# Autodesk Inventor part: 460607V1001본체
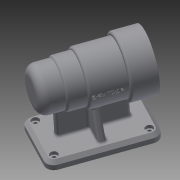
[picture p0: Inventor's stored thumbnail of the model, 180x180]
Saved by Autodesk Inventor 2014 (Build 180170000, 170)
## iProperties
Created: 2016-06
Part Number: 460607V1001본체
Material: 일반
Document SubType Name: Modeling
Designer: SEC
Density: 1 g/cm^3
Appearance: 기본값
Author: SEC
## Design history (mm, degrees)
sketch "스케치1"
  geometry: L1 (-56, 0)-(56, 0); L2 (-56, 0)-(-56, 25); L3 (-56, 25)-(-31, 25); L4 (-31, 25)-(-31, 27); L5 (-31, 27)-(-11, 27); L6 (-11, 27)-(-11, 30); L7 (-11, 30)-(28, 30); L8 (28, 30)-(28, 34); L9 (28, 34)-(56, 34); L10 (56, 34)-(56, 0); 2 further points
  constraints: 20 end point, 5 parallel, 4 perpendicular, 1 coincident, 1 horizontal, 1 midpoint
  dimensions: "d0" = 112 distance of L1.start L1.end; "d1" = 25 distance of L2.end L3.end; "d2" = 45 distance from line of L5.end L2; "d3" = 84 distance between parallel lines of L8 L2; "d4" = 50 diameter of L3 L1; "d5" = 54 diameter of L5 L1; "d6" = 60 diameter of L7 L1; "d7" = 68 diameter of L9 L1
revolve "회전1" sketch "스케치1" stored, may be unused: angle "d8" = 90 deg
node "작업 평면1"
sketch "스케치2"
  geometry: L1 (56, 35)-(-56, 35); L2 (-56, 35)-(-56, -35); L3 (-56, -35)-(56, -35); L4 (56, -35)-(56, 35); L5 (56, 35)-(-56, -35); L6 (-56, 35)-(56, -35); 1 further point
  constraints: 12 end point, 2 midpoint, 2 parallel, 1 horizontal, 1 perpendicular
  dimensions: "d10" = 112 distance of L2.end L3.end; "d11" = 70 distance of L1.end L2.end
extrude "돌출1" join sketch "스케치2" distance "d12" = 10; taper "d13" = 0 deg
sketch "스케치3"
  geometry: L1 (-36, 4)-(36, 4); L2 (36, 4)-(36, -4); L3 (36, -4)-(-36, -4); L4 (-36, -4)-(-36, 4); L5 (-36, 4)-(36, -4); L6 (36, 4)-(-36, -4); 1 further point
  constraints: 12 end point, 2 midpoint, 2 parallel, 1 horizontal, 1 perpendicular
  dimensions: "d14" = 8 distance of L1.end L2.end; "d15" = 72 distance of L1.start L1.end
extrude "돌출2" join sketch "스케치3" stored distance "d16" = 10; taper "d17" = 0 deg
sketch "스케치4"
  geometry: L1 (35, -60)-(-35, -60) reference; L2 (15.509, -25.68)-(28, -60); L3 (35, -70)-(35, -60) reference; A1 r 30 centre (0, 0) between (4, -29.732) and (-4, -29.732) reference; 1 further point
  constraints: 2 end point, 1 point on circle, 1 point on line
  dimensions: "d18" = 7 distance from line of L3 L2.end; "d19" = 110 deg angle of L1 L2
feature "리브1" sketch "스케치4" dims "d20" = 1, "d21" = 8, "d22" = 0, "d23" = 0, "d24" = 1, "d25" = 1
sketch "스케치5"
  geometry: C1 r 34 at (0, 0) reference; C2 r 21 at (0, 0)
  constraints: 1 centre point, 1 coincident
  dimensions: "d26" = 42 diameter of C2
extrude "돌출3" cut sketch "스케치5" distance "d27" = 15; taper "d28" = 0 deg
sketch "스케치6"
  geometry: C1 r 21 at (0, 0) reference; C2 r 24 at (0, 0)
  constraints: 1 centre point, 1 coincident
  dimensions: "d29" = 48 diameter of C2
extrude "돌출4" cut sketch "스케치6" distance "d30" = 54; taper "d31" = 0 deg
sketch "스케치9"
  geometry: C1 r 24 at (0, 0) reference; C2 r 21 at (0, 0)
  constraints: 1 centre point, 1 coincident
  dimensions: "d34" = 42 diameter of C2
extrude "돌출6" cut sketch "스케치9" distance "d35" = 12; taper "d36" = 0 deg
sketch "스케치10"
  geometry: C1 r 21 at (0, 0) reference; C2 r 17.5 at (0, 0)
  constraints: 1 centre point, 1 coincident
  dimensions: "d37" = 35 diameter of C2
extrude "돌출7" cut sketch "스케치10" distance "d38" = 18; taper "d39" = 0 deg
sketch "스케치11"
  geometry: C1 r 17.5 at (0, 0) reference; C2 r 16 at (0, 0)
  constraints: 1 centre point, 1 coincident
  dimensions: "d40" = 32 diameter of C2
extrude "돌출8" cut sketch "스케치11" distance "d41" = 4; taper "d42" = 0 deg
sketch "스케치12"
  geometry: C1 r 16 at (0, 0) reference; C2 r 10.5 at (0, 0)
  constraints: 1 centre point, 1 coincident
  dimensions: "d43" = 21 diameter of C2
extrude "돌출9" cut sketch "스케치12" distance "d44" = 3; taper "d45" = 0 deg
fillet "모깎기1" dims "d46" = 3
sketch "스케치13"
  geometry: L1 (56, 35)-(-56, 35) reference; L2 (-56, 35)-(-56, -35) reference; L3 (-56, -35)-(56, -35) reference; L4 (56, -35)-(56, 35) reference; L5 (-46, 25)-(46, 25); L6 (46, 25)-(46, -25); L7 (46, -25)-(-46, -25); L8 (-46, -25)-(-46, 25); 5 further points
  constraints: 8 end point, 4 coincident, 3 other
  dimensions: "d47" = 92 distance of L5.start L5.end; "d48" = 50 distance of L7.end L5.start (derived)
hole "구멍1" sketch "스케치13" at (-46, 25), (46, 25), (46, -25), (-46, -25) diameter "d49" = 5; stored, may be unused: countersink angle "d53" = 90 deg, drill point angle "d55" = 118 deg; dims "d50" = 6, "d51" = 9, "d52" = 4, "d54" = 10
fillet "모깎기2" dims "d56" = 10
fillet "모깎기3" dims "d57" = 10
sketch "스케치14"
  geometry: C1 r 21 at (0, 0) reference; 1 further point
  constraints: 1 horizontal alignment
  dimensions: "d58" = 26 distance of C1.centre point (26, 0)
hole "구멍2" sketch "스케치14" at (26, 0) diameter "d59" = 3.242; stored, may be unused: countersink angle "d63" = 90 deg, drill point angle "d65" = 118 deg; dims "d60" = 8, "d61" = 9, "d62" = 4, "d64" = 11
node "작업 평면2"
sketch "스케치15"
  geometry: L1 (47.5, -34)-(47.5, 34) reference; 2 further points
  constraints: 1 horizontal alignment, 1 other
  dimensions: "d69" = 48 distance from line of point (-0.5, 0) L1
feature "엠보싱1" sketch "스케치15" dims "d0" = 112, "d13" = 0, "d70" = 0.5, "d71" = 0
chamfer "모따기1" distance "d72" = 4; stored, may be unused: second distance "d73" = 2, angle "d74" = 45 deg
fillet "모깎기4" dims "d75" = 0.3
fillet "모깎기5" dims "d76" = 0.3
fillet "모깎기6" dims "d77" = 3
fillet "모깎기7" dims "d78" = 3
fillet "모깎기8" dims "d79" = 3
fillet "모깎기9" dims "d80" = 3
fillet "모깎기18" dims "d89" = 3
fillet "모깎기19" dims "d90" = 3
fillet "모깎기20" dims "d91" = 3
fillet "모깎기21" dims "d92" = 3
node "솔리드1"
mirror "대칭1"
pattern_circular "원형 패턴1" dims angle "d67" = 360 deg
